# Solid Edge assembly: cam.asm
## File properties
Author: Deepak Maini
Template: Normal.asm
Last saved by: CADCIM
Revision: 8
Application: Solid Edge
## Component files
cam.par
floorere.par
follower.par
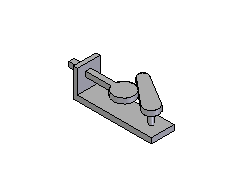
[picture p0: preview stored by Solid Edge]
